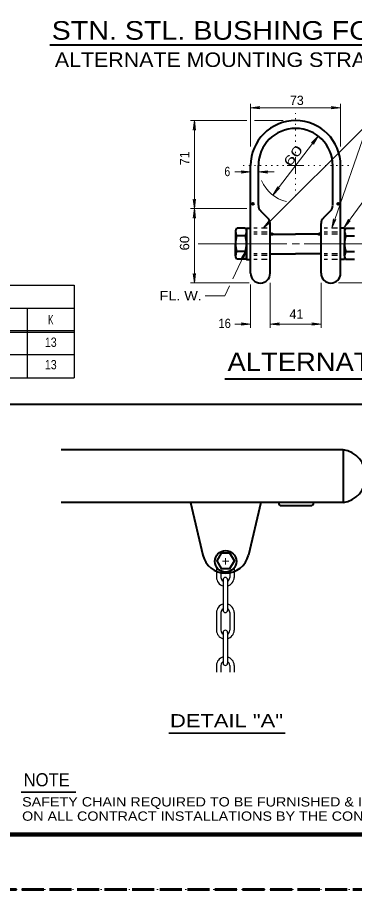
# Model space of a CAD drawing. Extents: x 312583 to 312854, y 144419 to 144597.
# Drawn here: x 312698.8 to 312726.3, y 144418.6 to 144489.8 of the extents above; entities that cross this region are included whole.
import ezdxf
from ezdxf.enums import TextEntityAlignment as Align

# ---------------------------------------------------------------- set-up
doc = ezdxf.new("R2010")
doc.units = 0
doc.header["$LTSCALE"] = 0.3
doc.header["$PDMODE"] = 32
doc.header["$PDSIZE"] = 0.15
for name, pattern in [('DOTTED', [1.5, 0.3, -1.2]), ('LONG_DASHED', [7.5, 6, -1.5]), ('SHORT_DASHED', [2.7, 1.5, -1.2])]:
    doc.linetypes.add(name, pattern=pattern)
for name, color, linetype, lineweight in [('1', 7, 'Continuous', 40), ('2', 7, 'Continuous', 40), ('62', 7, 'DOTTED', 13), ('63', 7, 'LONG_DASHED', 60)]:
    doc.layers.add(name, color=color, linetype=linetype, lineweight=lineweight)

msp = doc.modelspace()

# ---------------------------------------------------------------- linework, layer by layer
at = {"layer": '1'}
for p, q in [((312701.4873, 144487.5487), (312730.1686, 144487.5487)), ((312717.8617, 144468.907), (312717.8617, 144477.693)), ((312718.498, 144474.45), (312718.498, 144477.693)), ((312724.57, 144474.45), (312724.57, 144477.693)), ((312725.2063, 144468.907), (312725.2063, 144477.693)), ((312718.682, 144473.9976), (312719.2723, 144473.4073)), ((312724.386, 144473.9976), (312723.7957, 144473.4073)), ((312719.4563, 144468.907), (312719.4563, 144472.955)), ((312723.6117, 144468.907), (312723.6117, 144472.955)), ((312716.635, 144472.311), (312716.635, 144471.299)), ((312717.4553, 144472.5946), (312716.727, 144472.5946)), ((312717.5397, 144472.5793), (312717.8617, 144472.5793)), ((312717.5397, 144472.3186), (312717.5397, 144471.3066)), ((312725.5283, 144472.5793), (312725.2063, 144472.5793)), ((312725.5283, 144472.5793), (312725.5283, 144470.0263)), ((312725.5283, 144472.3186), (312725.5283, 144471.3066)), ((312725.6127, 144472.5946), (312726.341, 144472.5946)), ((312717.4553, 144471.9583), (312716.7193, 144471.9583)), ((312719.4563, 144472.104), (312721.534, 144472.104)), ((312723.6117, 144472.104), (312721.534, 144472.104)), ((312725.6127, 144471.9583), (312726.3487, 144471.9583)), ((312716.635, 144470.3253), (312716.635, 144471.3066)), ((312717.5397, 144470.3176), (312717.5397, 144471.3066)), ((312725.5283, 144470.3176), (312725.5283, 144471.3066)), ((312717.4553, 144470.6856), (312716.727, 144470.6856)), ((312719.4563, 144470.5016), (312721.534, 144470.5016)), ((312723.6117, 144470.5016), (312721.534, 144470.5016)), ((312725.6127, 144470.6856), (312726.341, 144470.6856)), ((312717.4553, 144470.0416), (312716.727, 144470.0416)), ((312725.5283, 144470.0263), (312725.2063, 144470.0263)), ((312725.6127, 144470.0416), (312726.341, 144470.0416)), ((312715.7627, 144460.2885), (312750.4184, 144460.2885)), ((312725.4034, 144454.486), (312702.4034, 144454.486)), ((312725.4034, 144454.486), (312725.4034, 144450.1773)), ((312725.4034, 144450.1773), (312702.4034, 144450.1773)), ((312712.9451, 144450.1773), (312713.9571, 144445.8993)), ((312718.6951, 144450.1773), (312717.6908, 144445.8993)), ((312720.3741, 144449.932), (312722.7738, 144449.932))]:
    msp.add_line(p, q, dxfattribs=at)
at = {"layer": '1', "lineweight": 13}
for p, q in [((312717.8617, 144479.2646), (312717.8617, 144482.7376)), ((312717.8617, 144482.4156), (312718.6283, 144482.5153)), ((312717.8617, 144482.4156), (312725.2063, 144482.4156)), ((312717.8617, 144482.4156), (312718.6283, 144482.3236)), ((312718.6283, 144482.5153), (312718.383, 144482.4156)), ((312718.6283, 144482.3236), (312718.383, 144482.4156)), ((312724.4397, 144482.5153), (312724.685, 144482.4156)), ((312725.2063, 144482.4156), (312724.4397, 144482.5153)), ((312724.4397, 144482.3236), (312724.685, 144482.4156)), ((312725.2063, 144482.4156), (312724.4397, 144482.3236)), ((312725.2063, 144479.2646), (312725.2063, 144482.7376)), ((312717.5627, 144481.3653), (312712.955, 144481.3653)), ((312713.277, 144481.3653), (312713.185, 144480.5986)), ((312713.185, 144480.5986), (312713.277, 144480.844)), ((312713.277, 144481.3653), (312713.369, 144480.5986)), ((312713.369, 144480.5986), (312713.277, 144480.844)), ((312720.5143, 144481.3653), (312718.1913, 144481.3653)), ((312718.8813, 144472.587), (312727.4603, 144481.1276)), ((312724.478, 144472.587), (312727.4603, 144481.1276)), ((312719.6863, 144475.2856), (312723.3817, 144480.1003)), ((312723.3817, 144480.1003), (312722.8373, 144479.5483)), ((312723.3817, 144480.1003), (312722.9907, 144479.4333)), ((312722.8373, 144479.5483), (312723.0673, 144479.6863)), ((312722.9907, 144479.4333), (312723.0673, 144479.6863)), ((312721.534, 144477.693), (312721.534, 144478.3753)), ((312717.0873, 144477.2713), (312717.3327, 144477.1793)), ((312717.8617, 144477.1793), (312717.0873, 144477.2713)), ((312718.498, 144477.1793), (312719.2647, 144477.2713)), ((312719.2647, 144477.2713), (312719.0193, 144477.1793)), ((312721.534, 144477.693), (312720.8517, 144477.693)), ((312721.534, 144477.693), (312721.534, 144477.0106)), ((312721.534, 144477.693), (312722.2163, 144477.693)), ((312717.8617, 144477.1793), (312716.5813, 144477.1793)), ((312717.0873, 144477.0796), (312717.3327, 144477.1793)), ((312717.8617, 144477.1793), (312717.0873, 144477.0796)), ((312718.498, 144477.1793), (312719.2647, 144477.0796)), ((312719.7783, 144477.1793), (312718.498, 144477.1793)), ((312719.2647, 144477.0796), (312719.0193, 144477.1793)), ((312719.6863, 144475.2856), (312720.0773, 144475.9526)), ((312719.6863, 144475.2856), (312720.2307, 144475.8376)), ((312720.0773, 144475.9526), (312720.0007, 144475.6996)), ((312720.2307, 144475.8376), (312720.0007, 144475.6996)), ((312727.698, 144475.669), (312725.4593, 144472.6253)), ((312713.185, 144474.9483), (312713.277, 144474.703)), ((312713.277, 144474.1816), (312713.185, 144474.9483)), ((312713.369, 144474.9483), (312713.277, 144474.703)), ((312713.277, 144474.1816), (312713.369, 144474.9483)), ((312717.5473, 144474.1816), (312712.955, 144474.1816)), ((312713.277, 144474.1816), (312713.185, 144473.415)), ((312713.185, 144473.415), (312713.277, 144473.6603)), ((312713.277, 144474.1816), (312713.369, 144473.415)), ((312713.369, 144473.415), (312713.277, 144473.6603)), ((312718.8813, 144472.587), (312719.3643, 144473.2003)), ((312718.8813, 144472.587), (312719.4947, 144473.0623)), ((312719.3643, 144473.2003), (312719.257, 144472.9626)), ((312719.4947, 144473.0623), (312719.257, 144472.9626)), ((312724.478, 144472.587), (312724.639, 144473.346)), ((312724.478, 144472.587), (312724.823, 144473.2846)), ((312724.639, 144473.346), (312724.6543, 144473.0853)), ((312724.823, 144473.2846), (312724.6543, 144473.0853)), ((312725.4593, 144472.6253), (312725.8427, 144473.3076)), ((312725.4593, 144472.6253), (312725.996, 144473.1926)), ((312725.8427, 144473.3076), (312725.7737, 144473.047)), ((312725.996, 144473.1926), (312725.7737, 144473.047)), ((312720.8287, 144471.3066), (312713.5717, 144471.3066)), ((312716.4127, 144468.4393), (312717.5397, 144470.8236)), ((312717.5397, 144470.8236), (312717.1257, 144470.172)), ((312717.5397, 144470.8236), (312717.2943, 144470.0876)), ((312721.856, 144471.3066), (312721.2657, 144471.3066)), ((312722.2393, 144471.3066), (312732.344, 144471.3066)), ((312717.1257, 144470.172), (312717.3173, 144470.3483)), ((312717.2943, 144470.0876), (312717.3173, 144470.3483)), ((312713.185, 144468.884), (312713.277, 144468.6386)), ((312713.277, 144468.1096), (312713.185, 144468.884)), ((312713.369, 144468.884), (312713.277, 144468.6386)), ((312713.277, 144468.1096), (312713.369, 144468.884)), ((312717.739, 144468.1096), (312712.955, 144468.1096)), ((312717.8617, 144464.4373), (312717.8617, 144467.9946)), ((312719.4563, 144464.4373), (312719.4563, 144468.1096)), ((312723.6117, 144464.4373), (312723.6117, 144468.1096)), ((312725.0453, 144468.1096), (312741.7127, 144468.1096)), ((312715.761, 144467.0593), (312716.1443, 144467.8643)), ((312714.1663, 144467.0593), (312715.761, 144467.0593)), ((312717.8617, 144464.7593), (312716.5813, 144464.7593)), ((312717.0873, 144464.8513), (312717.3327, 144464.7593)), ((312717.8617, 144464.7593), (312717.0873, 144464.8513)), ((312717.0873, 144464.6596), (312717.3327, 144464.7593)), ((312717.8617, 144464.7593), (312717.0873, 144464.6596)), ((312719.4563, 144464.7593), (312720.223, 144464.8513)), ((312719.4563, 144464.7593), (312723.6117, 144464.7593)), ((312719.4563, 144464.7593), (312720.223, 144464.6596)), ((312720.223, 144464.8513), (312719.9777, 144464.7593)), ((312720.223, 144464.6596), (312719.9777, 144464.7593)), ((312722.845, 144464.8513), (312723.0903, 144464.7593)), ((312723.6117, 144464.7593), (312722.845, 144464.8513)), ((312722.845, 144464.6596), (312723.0903, 144464.7593)), ((312723.6117, 144464.7593), (312722.845, 144464.6596)), ((312715.8201, 144445.3856), (312715.5671, 144445.3856)), ((312715.8201, 144445.3856), (312715.8201, 144445.6386)), ((312715.8201, 144445.3856), (312716.0808, 144445.3856)), ((312715.8201, 144445.3856), (312715.8201, 144445.125))]:
    msp.add_line(p, q, dxfattribs=at)
at = {"layer": '1', "linetype": 'DOTTED', "lineweight": 13}
for p, q in [((312721.534, 144478.7126), (312721.534, 144481.971)), ((312720.568, 144477.693), (312716.9263, 144477.693)), ((312722.5537, 144477.693), (312726.0267, 144477.693)), ((312721.534, 144476.6733), (312721.534, 144474.9176))]:
    msp.add_line(p, q, dxfattribs=at)
at = {"layer": '1', "linetype": 'SHORT_DASHED', "lineweight": 25}
for p, q in [((312719.2033, 144472.5793), (312718.1147, 144472.5793)), ((312719.2033, 144472.265), (312718.1147, 144472.265)), ((312724.9533, 144472.5793), (312723.8647, 144472.5793)), ((312724.9533, 144472.265), (312723.8647, 144472.265)), ((312719.2033, 144472.104), (312718.1147, 144472.104)), ((312724.9533, 144472.104), (312723.8647, 144472.104)), ((312719.2033, 144470.5016), (312718.1147, 144470.5016)), ((312719.2033, 144470.3483), (312718.1147, 144470.3483)), ((312724.9533, 144470.5016), (312723.8647, 144470.5016)), ((312724.9533, 144470.3483), (312723.8647, 144470.3483)), ((312719.2033, 144470.0263), (312718.1147, 144470.0263)), ((312724.9533, 144470.0263), (312723.8647, 144470.0263))]:
    msp.add_line(p, q, dxfattribs=at)
at = {"layer": '1', "lineweight": 25}
for p, q in [((312655.0815, 144467.9407), (312703.4735, 144467.9407)), ((312703.4735, 144467.9407), (312703.4735, 144460.3737)), ((312655.0815, 144466.0471), (312703.4735, 144466.0471)), ((312699.6401, 144466.0471), (312699.6401, 144460.3737)), ((312655.0815, 144464.2224), (312703.4735, 144464.2224)), ((312655.0815, 144464.0921), (312703.4735, 144464.0921)), ((312655.0815, 144462.2674), (312703.4735, 144462.2674)), ((312655.0815, 144460.3737), (312703.4735, 144460.3737)), ((312715.0841, 144444.9103), (312715.0841, 144444.067)), ((312715.4444, 144444.5883), (312715.4444, 144444.067)), ((312716.1574, 144444.573), (312716.1574, 144444.067)), ((312716.5178, 144444.849), (312716.5178, 144444.067)), ((312715.6208, 144443.8906), (312715.6208, 144441.376)), ((312715.9811, 144443.8906), (312715.9811, 144441.376)), ((312715.0841, 144441.192), (312715.0841, 144439.7583)), ((312715.4444, 144441.192), (312715.4444, 144439.7583)), ((312716.1574, 144441.192), (312716.1574, 144439.7583)), ((312716.5178, 144441.192), (312716.5178, 144439.7583)), ((312715.6208, 144439.5743), (312715.6208, 144437.0596)), ((312715.9811, 144439.5743), (312715.9811, 144437.0596)), ((312715.0841, 144436.8833), (312715.0841, 144436.3313)), ((312715.4444, 144436.8833), (312715.4444, 144436.3313)), ((312716.1574, 144436.8833), (312716.1574, 144436.3313)), ((312716.5178, 144436.8833), (312716.5178, 144436.3313))]:
    msp.add_line(p, q, dxfattribs=at)
at = {"layer": '1', "lineweight": 35}
for p, q in [((312711.1808, 144431.3643), (312720.6774, 144431.3643)), ((312699.1328, 144426.5414), (312703.6098, 144426.5414))]:
    msp.add_line(p, q, dxfattribs=at)
at = {"layer": '1', "lineweight": 158}
msp.add_line((312616.5, 144423.0846), (312849, 144423.0846), dxfattribs=at)
at = {"layer": '1', "lineweight": 13}
msp.add_lwpolyline([(312713.277, 144468.1096), (312713.277, 144474.1816), (312713.277, 144481.3653)], dxfattribs=at)
at = {"layer": '1'}
msp.add_lwpolyline([(312717.5397, 144472.5793), (312717.5397, 144470.0263), (312717.8617, 144470.0263)], dxfattribs=at)
msp.add_lwpolyline([(312716.1804, 144446.0373), (312715.4598, 144446.0373), (312715.0994, 144445.4163), (312715.4598, 144444.7953), (312716.1804, 144444.7876), (312716.5408, 144445.4163)], close=True, dxfattribs=at)
msp.add_circle((312715.822, 144445.3818), 0.8786, dxfattribs=at)
for centre, radius, start, end in [((312721.534, 144477.693), 3.6749, 90, 180), ((312721.534, 144477.693), 3.6749, 0, 90), ((312721.534, 144477.693), 3.036, 90, 180), ((312721.534, 144477.693), 3.036, 0, 90), ((312719.1369, 144474.4463), 0.6389, 180, 225), ((312723.9311, 144474.4463), 0.6389, 315, 0), ((312718.8174, 144472.9587), 0.6389, 0, 45), ((312724.2506, 144472.9587), 0.6389, 135, 180), ((312718.1053, 144472.5531), 1.5067, 191.77014, 203.36365), ((312717.1576, 144472.299), 0.5262, 145.8703, 178.33743), ((312716.065, 144472.5531), 1.5067, 336.63635, 348.22986), ((312717.0127, 144472.299), 0.5262, 1.66257, 34.1297), ((312727.003, 144472.5531), 1.5067, 191.77014, 203.36365), ((312726.0553, 144472.299), 0.5262, 145.8703, 178.33743), ((312719.3486, 144471.2517), 2.7192, 164.99798, 178.595), ((312714.8217, 144471.2517), 2.7192, 1.405, 15.00202), ((312728.2463, 144471.2517), 2.7192, 164.99798, 178.595), ((312719.3486, 144471.3851), 2.7192, 181.405, 195.00202), ((312714.8217, 144471.3851), 2.7192, 344.99798, 358.595), ((312728.2463, 144471.3851), 2.7192, 181.405, 195.00202), ((312718.1053, 144470.0837), 1.5067, 156.63635, 168.22986), ((312717.1576, 144470.3378), 0.5262, 181.66257, 214.1297), ((312716.065, 144470.0837), 1.5067, 11.77014, 23.36365), ((312717.0127, 144470.3378), 0.5262, 325.8703, 358.33743), ((312727.003, 144470.0837), 1.5067, 156.63635, 168.22986), ((312726.0553, 144470.3378), 0.5262, 181.66257, 214.1297), ((312718.659, 144468.907), 0.7999, 180, 0), ((312724.409, 144468.907), 0.7999, 180, 0), ((312725.1006, 144452.3297), 2.1777, 278.04577, 81.95422), ((312720.3741, 144450.1735), 0.2396, 180, 270), ((312722.7699, 144450.1735), 0.2396, 270, 0), ((312715.822, 144446.3397), 1.9162, 193.28615, 346.71385)]:
    msp.add_arc(centre, radius, start, end, dxfattribs=at)
at = {"layer": '1', "lineweight": 13}
msp.add_arc((312721.534, 144477.693), 3.036, 203.83874, 255.87017, dxfattribs=at)
at = {"layer": '1', "lineweight": 25}
for centre, radius, start, end in [((312715.799, 144444.0689), 0.7188, 180, 255.64081), ((312715.799, 144444.0689), 0.3594, 180, 240.26429), ((312715.799, 144443.8887), 0.1792, 0, 180), ((312715.799, 144444.0689), 0.3594, 300.08825, 0), ((312715.799, 144444.0689), 0.7188, 284.51697, 0), ((312715.799, 144441.1939), 0.7188, 104.35919, 180), ((312715.799, 144441.1939), 0.7188, 0, 75.48303), ((312715.799, 144441.1939), 0.3594, 119.73571, 180), ((312715.799, 144441.3741), 0.1792, 180, 0), ((312715.799, 144441.1939), 0.3594, 0, 59.91175), ((312715.799, 144439.7564), 0.7188, 180, 255.64081), ((312715.799, 144439.7564), 0.3594, 180, 240.26429), ((312715.799, 144439.5762), 0.1792, 0, 180), ((312715.799, 144439.7564), 0.3594, 300.08825, 0), ((312715.799, 144439.7564), 0.7188, 284.51697, 0), ((312715.799, 144436.8814), 0.7188, 104.35919, 180), ((312715.799, 144436.8814), 0.7188, 0, 75.48303), ((312715.799, 144436.8814), 0.3594, 119.73571, 180), ((312715.799, 144437.0616), 0.1792, 180, 0), ((312715.799, 144436.8814), 0.3594, 0, 59.91175)]:
    msp.add_arc(centre, radius, start, end, dxfattribs=at)
at = {"layer": '1'}
for p in [(312718.0533, 144474.565), (312725.0147, 144474.565), (312719.5943, 144472.104), (312723.4737, 144472.104)]:
    msp.add_point(p, dxfattribs=at)
at = {"layer": '2'}
msp.add_line((312616.5, 144458.228), (312849, 144458.228), dxfattribs=at)
at = {"layer": '62'}
msp.add_lwpolyline([(312601.2, 144418.5846), (312853.5, 144418.5846), (312853.5, 144596.7846)], dxfattribs=at)
at = {"layer": '63'}
msp.add_line((312851.75, 144418.5846), (312583.526, 144418.5846), dxfattribs=at)

# ---------------------------------------------------------------- texts
at = {"layer": '1'}
for s, height, width, p in [('STN. STL. BUSHING FOR', 1.52, 1.15, (312715.525, 144487.9696)), ('ALTERNATE MOUNTING STRAP', 1.186, 1.1, (312715.1684, 144485.7471)), ('K', 0.76, 0.65, (312701.5568, 144464.7274)), ('13', 0.76, 0.85, (312701.5568, 144462.8941)), ('ALTERNATE MOUNTING STRAP', 1.52, 1.1, (312732.9946, 144460.9096)), ('13', 0.76, 0.85, (312701.5568, 144461.0608)), ('DETAIL "A"', 1.07, 1.25, (312715.8958, 144431.8385)), ('NOTE', 1.07, 0.95, (312701.2255, 144427.0156))]:
    msp.add_text(s, height=height, dxfattribs=dict(at, width=width)).set_placement(p, align=Align.CENTER)
for s, p in [('73', (312721.0674, 144482.6389)), ('41 ', (312721.0338, 144465.1877))]:
    msp.add_text(s, height=0.76, dxfattribs=at).set_placement(p)
msp.add_text('71 ', height=0.76, rotation=90, dxfattribs=at).set_placement((312712.8512, 144477.7268))
for rotation, width, p in [(52.455, 1.6, (312721.08, 144477.5461)), (90, 1.05, (312712.8512, 144470.7667))]:
    msp.add_text('60', height=0.76, rotation=rotation, dxfattribs=dict(at, width=width)).set_placement(p)
for s, width, p in [('6', 0.85, (312715.7229, 144476.8306)), ('FL. W.', 1.15, (312710.4366, 144466.6849)), ('16', 0.9, (312715.2353, 144464.4317)), ('SAFETY CHAIN REQUIRED TO BE FURNISHED & INSTALLED', 1.15, (312699.2156, 144425.3677)), ('ON ALL CONTRACT INSTALLATIONS BY THE CONTRACTOR', 1.15, (312699.2156, 144424.2014))]:
    msp.add_text(s, height=0.76, dxfattribs=dict(at, width=width)).set_placement(p)

doc.saveas('drawing.dxf')
